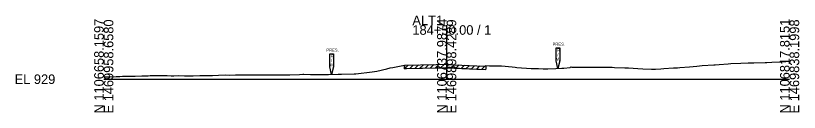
# Model space of a CAD drawing. Extents: x -26 to 2203, y -10 to 19568.
# Drawn here: x 1974.3 to 2202.8, y 6490.3 to 6518.6 of the extents above; entities that cross this region are included whole.
import ezdxf

# ---------------------------------------------------------------- set-up
doc = ezdxf.new("R2010")
doc.units = 0
for name, color, linetype in [('RD_GPK_XS_Cell', 7, 'Continuous'), ('RD_XS_ExGround', 7, 'Continuous'), ('RD_XS_ExPaveRet', 7, 'Continuous'), ('RD_XS_ExRW', 7, 'Continuous')]:
    doc.layers.add(name, color=color, linetype=linetype)

msp = doc.modelspace()

# ---------------------------------------------------------------- linework, layer by layer
at = {"layer": 'RD_GPK_XS_Cell'}
for p, q in [((2100, 6500), (2100, 6515.8)), ((2000, 6500), (2100, 6500)), ((2100, 6500), (2200, 6500))]:
    msp.add_line(p, q, dxfattribs=at)
at = {"layer": 'RD_XS_ExGround'}
msp.add_lwpolyline([(2000, 6500.71), (2001.68, 6500.72), (2003.58, 6500.79), (2004.64, 6500.81), (2005.44, 6500.85), (2008.56, 6500.91), (2009.2, 6500.93), (2011.07, 6501.04), (2012.95, 6501.04), (2013.54, 6501.06), (2016.71, 6501.08), (2017.49, 6501.07), (2018.53, 6501.05), (2019.63, 6500.99), (2020.47, 6501.04), (2021.78, 6501.05), (2023.51, 6501.01), (2024.23, 6501), (2026.06, 6501), (2027.99, 6501.1), (2028.49, 6501.11), (2031.74, 6501.13), (2033.47, 6501.21), (2035.5, 6501.26), (2036.77, 6501.15), (2038.45, 6501.27), (2039.26, 6501.27), (2041.75, 6501.3), (2043.02, 6501.3), (2043.43, 6501.29), (2046.78, 6501.28), (2048.41, 6501.27), (2050.53, 6501.26), (2053.39, 6501.3), (2054.29, 6501.28), (2057.06, 6501.4), (2058.05, 6501.44), (2058.37, 6501.45), (2060.33, 6501.4), (2061.81, 6501.38), (2062.47, 6501.38), (2063.35, 6501.38), (2065.57, 6501.43), (2068.34, 6501.46), (2069.32, 6501.49), (2073.06, 6501.56), (2073.46, 6501.58), (2074.28, 6501.67), (2077.47, 6502.06), (2078.3, 6502.17), (2079.61, 6502.33), (2082.5, 6503.06), (2083.5, 6503.34), (2084.28, 6503.47), (2086.24, 6503.82), (2087.71, 6504.11), (2096.97, 6504.32), (2099.58, 6504.37), (2100, 6504.35), (2108.79, 6503.92), (2111.37, 6503.83), (2111.4, 6503.98), (2112.45, 6503.95), (2113.14, 6503.92), (2114.65, 6503.94), (2116.02, 6503.9), (2119.1, 6503.6), (2119.96, 6503.52), (2120.5, 6503.46), (2124.59, 6503.11), (2125.7, 6503.13), (2126.73, 6503.14), (2128.11, 6503.05), (2129.45, 6503.03), (2131.81, 6503.11), (2133.6, 6503.22), (2134.21, 6503.26), (2135.97, 6503.43), (2136.23, 6503.59), (2136.45, 6503.48), (2141.75, 6503.51), (2143.05, 6503.53), (2144.49, 6503.53), (2148.24, 6503.5), (2148.9, 6503.47), (2152, 6503.36), (2152.44, 6503.34), (2153.01, 6503.32), (2155.73, 6503.14), (2157.21, 6503.07), (2159.71, 6502.92), (2160.18, 6502.92), (2160.85, 6502.93), (2162.42, 6503.05), (2163.33, 6503.12), (2166.1, 6503.3), (2167.35, 6503.37), (2167.96, 6503.41), (2170.79, 6503.66), (2172.94, 6503.86), (2174.55, 6503.99), (2177.92, 6504.2), (2178.31, 6504.24), (2179.51, 6504.32), (2182.07, 6504.52), (2182.9, 6504.59), (2185.83, 6504.74), (2187.88, 6504.8), (2189.58, 6504.83), (2192.86, 6504.88), (2193.34, 6504.9), (2194.82, 6504.97), (2197.1, 6505.08), (2197.84, 6505.12), (2200, 6505.27)], dxfattribs=at)
at = {"layer": 'RD_XS_ExPaveRet'}
for p, q in [((2087.71, 6503.02), (2088.81, 6504.12)), ((2087.71, 6504.11), (2087.71, 6503.11)), ((2089.21, 6503.13), (2090.24, 6504.15)), ((2090.71, 6503.16), (2091.74, 6504.18)), ((2092.21, 6503.2), (2093.24, 6504.22)), ((2093.71, 6503.23), (2094.74, 6504.25)), ((2095.21, 6503.26), (2096.24, 6504.28)), ((2096.71, 6503.29), (2097.74, 6504.32)), ((2098.21, 6503.33), (2099.23, 6504.35)), ((2099.71, 6503.36), (2100.67, 6504.32)), ((2101.21, 6503.31), (2102.15, 6504.25)), ((2102.71, 6503.24), (2103.65, 6504.17)), ((2104.21, 6503.17), (2105.15, 6504.1)), ((2087.71, 6503.02), (2087.71, 6504)), ((2087.71, 6503.11), (2096.97, 6503.32)), ((2087.71, 6503.02), (2088.27, 6503.13)), ((2087.71, 6503), (2088.27, 6503.11)), ((2088.27, 6503.13), (2097.36, 6503.33)), ((2088.27, 6503.11), (2097.58, 6503.31)), ((2096.97, 6503.32), (2099.58, 6503.37)), ((2097.36, 6503.33), (2100.13, 6503.39)), ((2097.58, 6503.31), (2100.13, 6503.37)), ((2099.58, 6503.37), (2100, 6503.35)), ((2100, 6503.35), (2108.79, 6502.92)), ((2100.13, 6503.39), (2109.22, 6502.94)), ((2100.13, 6503.37), (2109.44, 6502.91)), ((2105.71, 6503.09), (2106.65, 6504.03)), ((2107.21, 6503.02), (2108.15, 6503.96)), ((2108.71, 6502.95), (2109.66, 6503.89)), ((2108.79, 6502.92), (2111.37, 6502.83)), ((2109.22, 6502.94), (2111.4, 6502.86)), ((2109.44, 6502.91), (2111.4, 6502.84)), ((2110.21, 6502.91), (2111.15, 6503.84)), ((2111.37, 6502.83), (2111.4, 6502.98)), ((2111.4, 6503.98), (2111.4, 6502.98)), ((2111.4, 6503.98), (2111.4, 6502.98))]:
    msp.add_line(p, q, dxfattribs=at)
at = {"layer": 'RD_XS_ExRW'}
for points in [[(2131.9, 6509.16), (2132.99, 6509.16), (2132.99, 6505.33), (2132.45, 6503.14), (2131.9, 6505.33)], [(2065.9, 6507.45), (2066.99, 6507.45), (2066.99, 6503.62), (2066.44, 6501.43), (2065.9, 6503.62)]]:
    msp.add_lwpolyline(points, close=True, dxfattribs=at)

# ---------------------------------------------------------------- texts
at = {"layer": 'RD_GPK_XS_Cell'}
for s, p in [('ALT1', (2090, 6515.8)), ('184+50.00 / 1', (2090, 6513)), ('EL 929', (1974, 6498.6))]:
    msp.add_text(s, height=2.8, dxfattribs=at).set_placement(p)
for s, p in [('N 1106658.1597', (2000, 6490)), ('E 1469958.6580', (2002.8, 6490)), ('N 1106737.9874', (2100, 6490)), ('E 1469898.4289', (2102.8, 6490)), ('N 1106817.8151', (2200, 6490)), ('E 1469838.1998', (2202.8, 6490))]:
    msp.add_text(s, height=2.8, rotation=90, dxfattribs=at).set_placement(p)
at = {"layer": 'RD_XS_ExRW'}
for s, p in [('PRES.', (2064.9, 6508.08)), ('PRES.', (2130.9, 6509.79)), ('R', (2132.16, 6508.07)), ('R', (2066.16, 6506.36)), ('/', (2132.28, 6506.75)), ('W', (2065.97, 6503.73)), ('/', (2066.28, 6505.05)), ('W', (2131.97, 6505.44))]:
    msp.add_text(s, height=0.875, dxfattribs=at).set_placement(p)

doc.saveas('drawing.dxf')
